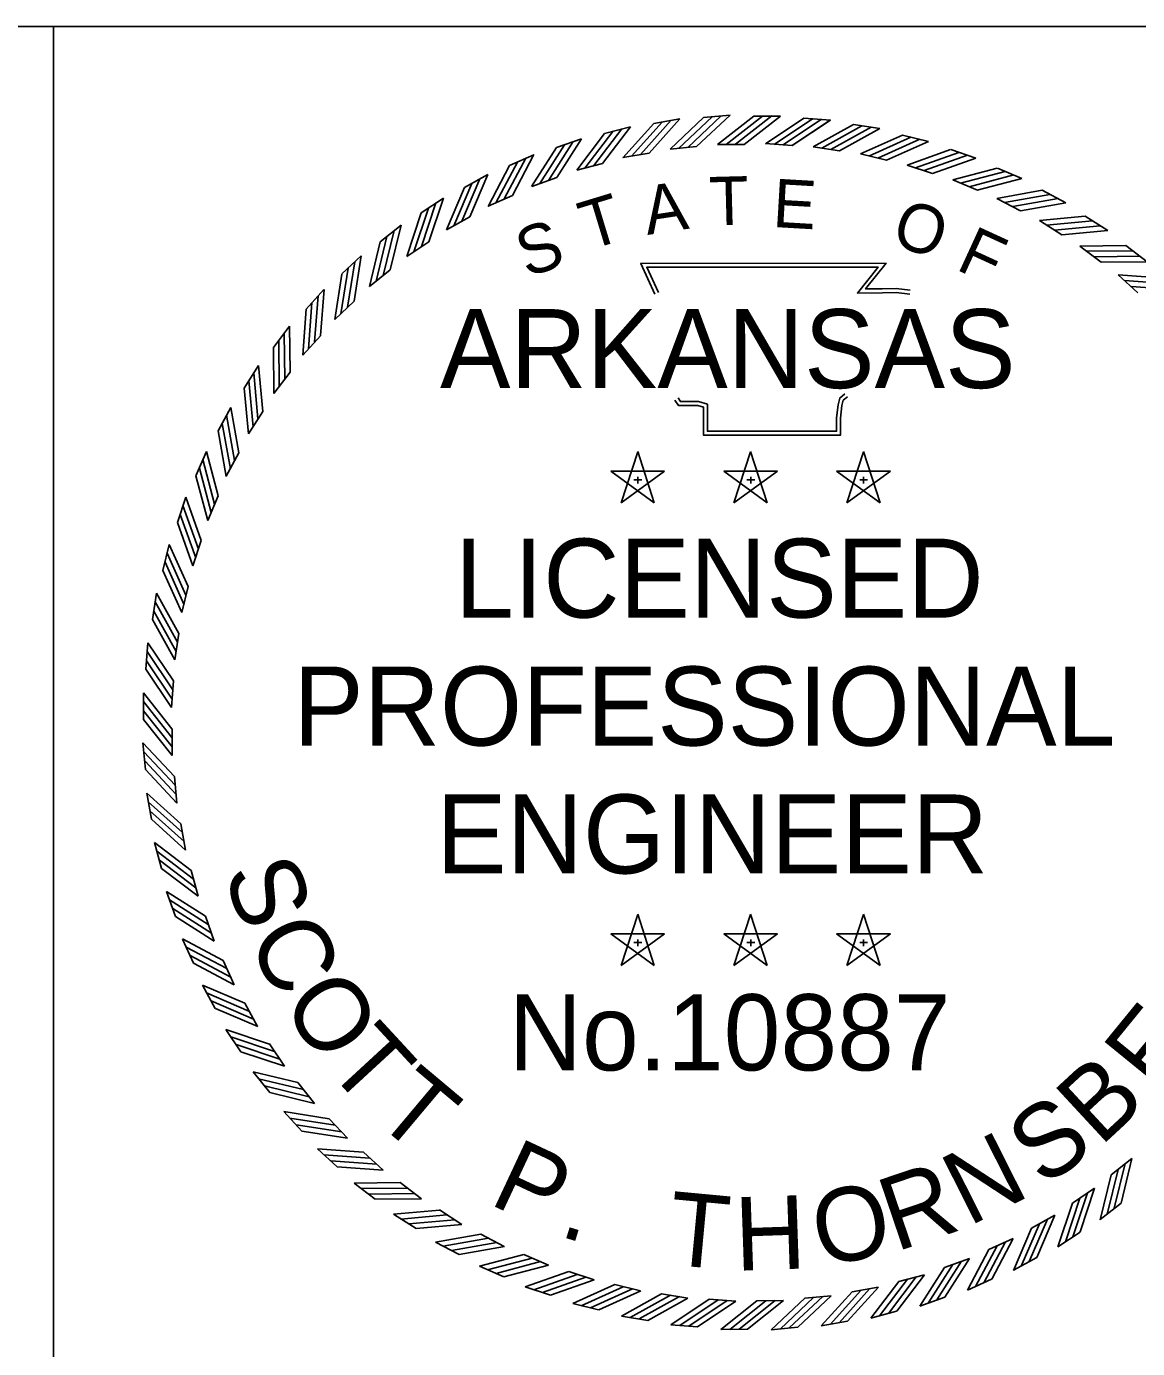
# Model space of a CAD drawing. Extents: x 0 to 1228740, y 0 to 152440.
# Drawn here: x 30.877 to 32.858, y 17.785 to 20.143 of the extents above; entities that cross this region are included whole.
import ezdxf

# ---------------------------------------------------------------- set-up
doc = ezdxf.new("R2010")
doc.units = 0
for name, color, linetype in [('R_Border', 7, 'Continuous'), ('R_No Plot', 7, 'Continuous'), ('STAMP', 7, 'Continuous'), ('STAMP_KLL', 7, 'Continuous')]:
    doc.layers.add(name, color=color, linetype=linetype)

# ---------------------------------------------------------------- blocks, each defined once
blk = doc.blocks.new('AR_SPT')
at = {"layer": 'R_No Plot'}
blk.add_lwpolyline([(-0.10028, 0.09468), (0.09697, 0.09468), (0.09697, -0.10257), (-0.10028, -0.10257)], close=True, dxfattribs=at)
at = {"layer": 'STAMP'}
for p, q in [((-0.01536, 0.08094), (-0.01165, 0.08159)), ((-0.00831, 0.08178), (-0.00456, 0.08212)), ((-0.00118, 0.08199), (0.00259, 0.08199)), ((0.00588, 0.08171), (0.00964, 0.08143)), ((0.00588, 0.08171), (0.00963, 0.08143)), ((0.01291, 0.08079), (0.01663, 0.08021)), ((-0.02912, 0.07752), (-0.02557, 0.07878)), ((-0.02231, 0.07951), (-0.01867, 0.08047)), ((0.01985, 0.0793), (0.02351, 0.07841)), ((-0.01972, 0.0761), (-0.016, 0.07675)), ((-0.01306, 0.07732), (-0.0093, 0.07766)), ((-0.00632, 0.07798), (-0.00254, 0.07798)), ((0.00045, 0.07809), (0.00422, 0.07781)), ((0.00046, 0.07809), (0.00422, 0.07781)), ((0.00721, 0.07763), (0.01094, 0.07705)), ((0.02665, 0.07724), (0.03022, 0.07605)), ((-0.03575, 0.07498), (-0.03232, 0.07652)), ((-0.02626, 0.07433), (-0.02261, 0.07529)), ((0.01391, 0.07662), (0.01758, 0.07573)), ((0.0205, 0.07506), (0.02409, 0.07387)), ((-0.04214, 0.07189), (-0.03885, 0.07372)), ((-0.03263, 0.07203), (-0.02907, 0.07329)), ((0.03325, 0.07463), (0.03671, 0.07314)), ((0.02694, 0.07296), (0.03042, 0.07148)), ((0.03961, 0.07148), (0.04293, 0.06971)), ((-0.04826, 0.06829), (-0.04512, 0.07038)), ((-0.03879, 0.06922), (-0.03535, 0.07076)), ((0.03319, 0.07034), (0.03653, 0.06857)), ((-0.0447, 0.0659), (-0.0414, 0.06773)), ((0.04568, 0.06781), (0.04886, 0.06578)), ((-0.05406, 0.0642), (-0.05111, 0.06654)), ((0.0392, 0.06721), (0.04238, 0.06517)), ((-0.05031, 0.06211), (-0.04717, 0.0642)), ((0.05144, 0.06366), (0.05443, 0.06137)), ((-0.0595, 0.05964), (-0.05675, 0.06221)), ((0.04492, 0.06359), (0.04792, 0.0613)), ((-0.05559, 0.05786), (-0.05263, 0.06021)), ((0.05033, 0.05951), (0.05313, 0.05698)), ((-0.06454, 0.05464), (-0.06202, 0.05744)), ((-0.0605, 0.0532), (-0.05775, 0.05578)), ((-0.06915, 0.04925), (-0.06687, 0.05224)), ((-0.06501, 0.04814), (-0.06248, 0.05094)), ((-0.07331, 0.04349), (-0.07128, 0.04667)), ((-0.06909, 0.04273), (-0.0668, 0.04573)), ((-0.07697, 0.03742), (-0.07521, 0.04074)), ((-0.07271, 0.03701), (-0.07067, 0.04018)), ((-0.08012, 0.03105), (-0.07864, 0.03452)), ((-0.07584, 0.031), (-0.07407, 0.03433)), ((-0.01763, 0.03448), (-0.01999, 0.02725)), ((-0.01529, 0.02725), (-0.01763, 0.03449)), ((-0.00166, 0.03448), (-0.00402, 0.02725)), ((0.00069, 0.02725), (-0.00166, 0.03449)), ((0.01431, 0.03448), (0.01196, 0.02725)), ((0.01666, 0.02725), (0.01432, 0.03449)), ((-0.01384, 0.03172), (-0.02144, 0.03173)), ((-0.02143, 0.03172), (-0.01528, 0.02725)), ((-0.01998, 0.02725), (-0.01383, 0.03172)), ((-0.01817, 0.0305), (-0.01704, 0.0305)), ((-0.01763, 0.03091), (-0.01763, 0.02996)), ((0.00214, 0.03172), (-0.00546, 0.03173)), ((-0.00546, 0.03172), (0.00069, 0.02725)), ((-0.00401, 0.02725), (0.00215, 0.03172)), ((-0.0022, 0.0305), (-0.00107, 0.0305)), ((-0.00165, 0.03091), (-0.00165, 0.02996)), ((0.01811, 0.03172), (0.01051, 0.03173)), ((0.01051, 0.03172), (0.01666, 0.02725)), ((0.01196, 0.02725), (0.01812, 0.03172)), ((0.01377, 0.0305), (0.0149, 0.0305)), ((0.01432, 0.03091), (0.01432, 0.02996)), ((-0.07846, 0.02475), (-0.07698, 0.02822)), ((-0.08274, 0.02446), (-0.08155, 0.02803)), ((-0.0848, 0.01766), (-0.08391, 0.02132)), ((-0.08056, 0.01831), (-0.07937, 0.02189)), ((-0.08212, 0.01172), (-0.08123, 0.01539)), ((-0.08629, 0.01072), (-0.0857, 0.01444)), ((-0.08313, 0.00502), (-0.08254, 0.00875)), ((-0.0872, 0.00368), (-0.08693, 0.00744)), ((-0.08358, -0.00173), (-0.08331, 0.00203)), ((-0.08753, -0.00341), (-0.08757, 0.00036)), ((-0.08348, -0.00851), (-0.08351, -0.00473)), ((-0.08728, -0.0105), (-0.08762, -0.00675)), ((-0.08281, -0.01525), (-0.08316, -0.01149)), ((-0.08643, -0.01755), (-0.08709, -0.01384)), ((-0.08159, -0.02191), (-0.08225, -0.01819)), ((-0.08501, -0.0245), (-0.08597, -0.02086)), ((-0.07983, -0.02845), (-0.08079, -0.0248)), ((-0.08302, -0.03131), (-0.08428, -0.02776)), ((-0.07753, -0.03482), (-0.07879, -0.03126)), ((-0.01763, -0.03101), (-0.01999, -0.03824)), ((-0.01529, -0.03823), (-0.01763, -0.031)), ((-0.00166, -0.03101), (-0.00402, -0.03824)), ((0.00069, -0.03823), (-0.00166, -0.031)), ((0.01431, -0.03101), (0.01196, -0.03824)), ((0.01666, -0.03823), (0.01432, -0.031)), ((-0.08048, -0.03794), (-0.08202, -0.03451)), ((-0.01384, -0.03377), (-0.02144, -0.03376)), ((-0.02143, -0.03377), (-0.01528, -0.03824)), ((-0.01998, -0.03823), (-0.01383, -0.03377)), ((-0.01817, -0.03498), (-0.01704, -0.03498)), ((-0.01763, -0.03458), (-0.01763, -0.03553)), ((0.00214, -0.03377), (-0.00546, -0.03376)), ((-0.00546, -0.03377), (0.00069, -0.03824)), ((-0.00401, -0.03823), (0.00215, -0.03377)), ((-0.0022, -0.03498), (-0.00107, -0.03498)), ((-0.00165, -0.03458), (-0.00165, -0.03553)), ((0.01811, -0.03377), (0.01051, -0.03376)), ((0.01051, -0.03377), (0.01666, -0.03824)), ((0.01196, -0.03823), (0.01812, -0.03377)), ((0.01377, -0.03498), (0.0149, -0.03498)), ((0.01432, -0.03458), (0.01432, -0.03553)), ((-0.07471, -0.04098), (-0.07626, -0.03754)), ((-0.07739, -0.04433), (-0.07921, -0.04104)), ((-0.0714, -0.04689), (-0.07322, -0.04359)), ((-0.07379, -0.05045), (-0.07588, -0.04732)), ((-0.0676, -0.0525), (-0.0697, -0.04936)), ((-0.06969, -0.05625), (-0.07203, -0.0533)), ((-0.06336, -0.05778), (-0.06571, -0.05483)), ((-0.06513, -0.06169), (-0.06771, -0.05894)), ((-0.0587, -0.06269), (-0.06128, -0.05994)), ((-0.06014, -0.06673), (-0.06293, -0.06421)), ((-0.05364, -0.0672), (-0.05644, -0.06467)), ((0.05228, -0.06555), (0.04933, -0.0679)), ((-0.05475, -0.07135), (-0.05774, -0.06906)), ((-0.04823, -0.07128), (-0.05123, -0.06899)), ((0.047, -0.06979), (0.04386, -0.07189)), ((-0.0425, -0.0749), (-0.04568, -0.07286)), ((0.05075, -0.07188), (0.0478, -0.07422)), ((-0.04899, -0.0755), (-0.05216, -0.07347)), ((0.04139, -0.07359), (0.03809, -0.07541)), ((-0.0365, -0.07803), (-0.03983, -0.07626)), ((0.04495, -0.07598), (0.04182, -0.07807)), ((-0.04291, -0.07916), (-0.04624, -0.0774)), ((0.03549, -0.0769), (0.03204, -0.07845)), ((-0.03025, -0.08065), (-0.03372, -0.07917)), ((0.02933, -0.07972), (0.02577, -0.08098)), ((0.03884, -0.07958), (0.03554, -0.0814)), ((-0.03655, -0.08231), (-0.04001, -0.08083)), ((-0.02381, -0.08275), (-0.02739, -0.08156)), ((0.02295, -0.08202), (0.0193, -0.08298)), ((-0.02995, -0.08493), (-0.03353, -0.08374)), ((-0.01722, -0.08431), (-0.02089, -0.08342)), ((0.01641, -0.08379), (0.0127, -0.08444)), ((0.03244, -0.08267), (0.02901, -0.08421)), ((-0.01052, -0.08532), (-0.01425, -0.08473)), ((-0.00376, -0.08577), (-0.00753, -0.0855)), ((0.00301, -0.08567), (-0.00076, -0.0857)), ((0.00975, -0.085), (0.00599, -0.08535)), ((0.02582, -0.08521), (0.02227, -0.08647)), ((-0.02316, -0.08699), (-0.02682, -0.0861)), ((-0.01622, -0.08848), (-0.01994, -0.08789)), ((0.019, -0.0872), (0.01536, -0.08816)), ((-0.00918, -0.08939), (-0.01294, -0.08912)), ((-0.00209, -0.08972), (-0.00586, -0.08976)), ((0.005, -0.08947), (0.00125, -0.08981)), ((0.01205, -0.08862), (0.00834, -0.08928))]:
    blk.add_line(p, q, dxfattribs=at)
for points in [[(-0.02262, 0.07529), (-0.01867, 0.08048)], [(-0.01972, 0.07609), (-0.01536, 0.08093)], [(-0.01853, 0.07629), (-0.01417, 0.08113)], [(-0.01725, 0.07655), (-0.01288, 0.08139)], [(-0.01601, 0.07675), (-0.01165, 0.08159)], [(-0.01306, 0.07731), (-0.00831, 0.08177)], [(-0.01185, 0.07741), (-0.00711, 0.08187)], [(-0.01055, 0.07756), (-0.00581, 0.08202)], [(-0.0093, 0.07766), (-0.00456, 0.08213)], [(-0.00632, 0.07798), (-0.00118, 0.08198)], [(-0.00511, 0.07797), (0.00003, 0.08197)], [(-0.0038, 0.078), (0.00134, 0.082)], [(-0.00255, 0.07798), (0.00259, 0.08199)], [(0.00045, 0.07808), (0.00587, 0.08171)], [(0.00045, 0.07808), (0.00587, 0.0817)], [(0.00166, 0.07798), (0.00708, 0.08161)], [(0.00166, 0.07798), (0.00708, 0.0816)], [(0.00296, 0.07792), (0.00839, 0.08154)], [(0.00297, 0.07792), (0.00838, 0.08154)], [(0.00422, 0.07781), (0.00964, 0.08144)], [(0.00422, 0.07781), (0.00963, 0.08143)], [(0.00721, 0.07763), (0.01291, 0.08079)], [(0.00841, 0.07743), (0.0141, 0.08059)], [(-0.02908, 0.07329), (-0.02557, 0.07878)], [(-0.02626, 0.07433), (-0.02231, 0.07951)], [(-0.02509, 0.07463), (-0.02114, 0.07981)], [(-0.02383, 0.07499), (-0.01988, 0.08017)], [(0.0097, 0.07726), (0.0154, 0.08041)], [(0.01094, 0.07705), (0.01664, 0.08021)], [(0.01391, 0.07662), (0.01985, 0.0793)], [(0.01508, 0.07632), (0.02102, 0.079)], [(0.01636, 0.07604), (0.0223, 0.07872)], [(-0.03264, 0.07203), (-0.02913, 0.07752)], [(-0.03149, 0.07242), (-0.02798, 0.07791)], [(-0.03027, 0.07289), (-0.02676, 0.07838)], [(0.01758, 0.07573), (0.02352, 0.07841)], [(0.0205, 0.07506), (0.02664, 0.07724)], [(0.02165, 0.07467), (0.02779, 0.07684)], [(-0.0388, 0.06921), (-0.03575, 0.07497)], [(-0.03769, 0.0697), (-0.03464, 0.07546)], [(-0.0365, 0.07026), (-0.03346, 0.07602)], [(-0.03536, 0.07076), (-0.03231, 0.07653)], [(0.0229, 0.07428), (0.02904, 0.07646)], [(0.02408, 0.07387), (0.03022, 0.07605)], [(-0.0425, 0.06713), (-0.03995, 0.07312)], [(-0.0414, 0.06773), (-0.03885, 0.07372)], [(0.02694, 0.07296), (0.03324, 0.07462)], [(0.02805, 0.07247), (0.03435, 0.07414)], [(0.02926, 0.07199), (0.03556, 0.07365)], [(0.03041, 0.07148), (0.03671, 0.07315)], [(-0.0447, 0.06589), (-0.04214, 0.07189)], [(-0.04364, 0.06647), (-0.04108, 0.07246)], [(0.03318, 0.07034), (0.0396, 0.07148)], [(-0.04823, 0.06351), (-0.04617, 0.0697)], [(-0.04718, 0.0642), (-0.04512, 0.07038)], [(0.03425, 0.06976), (0.04067, 0.0709)], [(0.03542, 0.06917), (0.04183, 0.07031)], [(0.03652, 0.06858), (0.04294, 0.06971)], [(-0.05031, 0.0621), (-0.04826, 0.06828)], [(-0.0493, 0.06276), (-0.04725, 0.06895)], [(0.03919, 0.06721), (0.04568, 0.06781)], [(-0.05363, 0.05944), (-0.05209, 0.06577)], [(-0.05264, 0.06021), (-0.0511, 0.06654)], [(0.04021, 0.06654), (0.04669, 0.06715)], [(0.04132, 0.06586), (0.04781, 0.06647)], [(0.04237, 0.06518), (0.04886, 0.06578)], [(-0.05559, 0.05786), (-0.05406, 0.06419)], [(-0.05464, 0.0586), (-0.0531, 0.06493)], [(0.04492, 0.06359), (0.05143, 0.06366)], [(-0.05775, 0.05578), (-0.05675, 0.06222)], [(0.04588, 0.06285), (0.05239, 0.06291)], [(0.04693, 0.06208), (0.05345, 0.06214)], [(-0.05961, 0.05401), (-0.05861, 0.06045)], [(-0.05868, 0.05493), (-0.05767, 0.06137)], [(-0.01521, 0.05679), (-0.01721, 0.06113), (0.01751, 0.06115), (0.01461, 0.05751), (0.01697, 0.05754), (0.01894, 0.05756), (0.02091, 0.05735)], [(-0.01471, 0.05702), (-0.01635, 0.06058), (0.01637, 0.0606), (0.01346, 0.05694), (0.01698, 0.05699), (0.01892, 0.05701), (0.02085, 0.0568)], [(0.04792, 0.06131), (0.05444, 0.06137)], [(-0.0605, 0.05319), (-0.0595, 0.05963)], [(0.05033, 0.05952), (0.05683, 0.05904)], [(0.05122, 0.05869), (0.05772, 0.05822)], [(-0.06334, 0.05002), (-0.06286, 0.05652)], [(-0.06249, 0.05094), (-0.06201, 0.05744)], [(0.05221, 0.05784), (0.05871, 0.05737)], [(-0.06501, 0.04814), (-0.06454, 0.05464)], [(-0.06419, 0.04903), (-0.06372, 0.05553)], [(-0.06757, 0.04474), (-0.06764, 0.05126)], [(-0.0668, 0.04573), (-0.06687, 0.05225)], [(-0.06909, 0.04273), (-0.06916, 0.04924)], [(-0.06834, 0.04368), (-0.06841, 0.0502)], [(-0.07136, 0.03913), (-0.07196, 0.04562)], [(-0.07067, 0.04018), (-0.07128, 0.04667)], [(-0.0727, 0.037), (-0.07331, 0.04349)], [(-0.07204, 0.03801), (-0.07265, 0.0445)], [(0.01204, 0.04223), (0.01145, 0.04175), (0.01125, 0.04103), (0.01106, 0.03923), (0.01106, 0.03683), (-0.00833, 0.03683), (-0.00833, 0.04007), (-0.00833, 0.04079), (-0.00912, 0.04103), (-0.01187, 0.04103), (-0.01236, 0.04178)], [(0.01169, 0.04266), (0.01096, 0.04207), (0.01071, 0.04113), (0.01051, 0.03926), (0.01051, 0.03738), (-0.00778, 0.03738), (-0.00778, 0.04007), (-0.00778, 0.0412), (-0.00903, 0.04158), (-0.01158, 0.04158), (-0.0119, 0.04208)], [(-0.07467, 0.03323), (-0.07581, 0.03964)], [(-0.07407, 0.03433), (-0.07521, 0.04075)], [(-0.07526, 0.03206), (-0.0764, 0.03847)], [(-0.07583, 0.03099), (-0.07697, 0.03741)], [(-0.07698, 0.02822), (-0.07864, 0.03452)], [(-0.07797, 0.02586), (-0.07964, 0.03216)], [(-0.07748, 0.02707), (-0.07915, 0.03337)], [(-0.07846, 0.02475), (-0.08012, 0.03105)], [(-0.07978, 0.0207), (-0.08196, 0.02685)], [(-0.07937, 0.02189), (-0.08155, 0.02803)], [(-0.08056, 0.01831), (-0.08274, 0.02445)], [(-0.08016, 0.01945), (-0.08234, 0.0256)], [(-0.08123, 0.01539), (-0.08391, 0.02133)], [(-0.08182, 0.01289), (-0.0845, 0.01883)], [(-0.08154, 0.01417), (-0.08422, 0.02011)], [(-0.08212, 0.01172), (-0.08479, 0.01766)], [(-0.08275, 0.00751), (-0.08591, 0.01321)], [(-0.08255, 0.00875), (-0.08571, 0.01445)], [(-0.08293, 0.00621), (-0.08609, 0.01191)], [(-0.08313, 0.00502), (-0.08629, 0.01072)], [(-0.08341, 0.00078), (-0.08703, 0.00619)], [(-0.08331, 0.00203), (-0.08693, 0.00744)], [(-0.08348, -0.00053), (-0.0871, 0.00489)], [(-0.08358, -0.00174), (-0.0872, 0.00368)], [(-0.08352, -0.00474), (-0.08757, 0.00036)], [(-0.08352, -0.00599), (-0.08757, -0.00089)], [(-0.08347, -0.0073), (-0.08753, -0.0022)], [(-0.08347, -0.00851), (-0.08753, -0.00341)], [(-0.08316, -0.01149), (-0.08762, -0.00675)], [(-0.08306, -0.01274), (-0.08752, -0.008)], [(-0.08291, -0.01404), (-0.08737, -0.0093)], [(-0.08281, -0.01525), (-0.08727, -0.0105)], [(-0.08225, -0.0182), (-0.08709, -0.01384)], [(-0.08205, -0.01944), (-0.08688, -0.01507)], [(-0.08179, -0.02072), (-0.08663, -0.01636)], [(-0.08159, -0.02192), (-0.08643, -0.01755)], [(-0.08079, -0.02481), (-0.08597, -0.02086)], [(-0.08048, -0.02602), (-0.08567, -0.02207)], [(-0.08012, -0.02728), (-0.0853, -0.02333)], [(-0.07983, -0.02845), (-0.08501, -0.02451)], [(-0.07879, -0.03127), (-0.08428, -0.02776)], [(-0.07838, -0.03246), (-0.08387, -0.02895)], [(-0.07792, -0.03368), (-0.08341, -0.03017)], [(-0.07753, -0.03483), (-0.08302, -0.03132)], [(-0.07626, -0.03755), (-0.08202, -0.0345)], [(-0.07576, -0.03869), (-0.08152, -0.03565)], [(-0.0752, -0.03988), (-0.08096, -0.03683)], [(-0.07471, -0.04099), (-0.08047, -0.03794)], [(-0.07322, -0.04359), (-0.07922, -0.04104)], [(-0.07263, -0.0447), (-0.07862, -0.04214)], [(-0.07197, -0.04583), (-0.07796, -0.04327)], [(-0.07139, -0.04689), (-0.07738, -0.04434)], [(-0.0697, -0.04937), (-0.07588, -0.04731)], [(-0.06901, -0.05042), (-0.07519, -0.04836)], [(-0.06826, -0.05149), (-0.07445, -0.04944)], [(-0.0676, -0.0525), (-0.07378, -0.05045)], [(-0.06571, -0.05483), (-0.07204, -0.0533)], [(-0.06493, -0.05582), (-0.07127, -0.05429)], [(-0.0641, -0.05683), (-0.07043, -0.05529)], [(-0.06336, -0.05778), (-0.06969, -0.05625)], [(-0.06128, -0.05995), (-0.06771, -0.05894)], [(-0.06043, -0.06087), (-0.06686, -0.05986)], [(-0.05951, -0.0618), (-0.06595, -0.0608)], [(-0.05869, -0.06269), (-0.06513, -0.06169)], [(-0.05644, -0.06468), (-0.06294, -0.06421)], [(-0.05552, -0.06553), (-0.06202, -0.06506)], [(-0.05453, -0.06638), (-0.06103, -0.06591)], [(-0.05364, -0.0672), (-0.06013, -0.06673)], [(0.05032, -0.06713), (0.04879, -0.07346)], [(0.05133, -0.06629), (0.04979, -0.07262)], [(0.05229, -0.06555), (0.05075, -0.07188)], [(-0.05123, -0.06899), (-0.05774, -0.06906)], [(0.04933, -0.0679), (0.0478, -0.07423)], [(-0.05024, -0.06976), (-0.05675, -0.06983)], [(-0.04918, -0.07054), (-0.0557, -0.0706)], [(0.04599, -0.07045), (0.04394, -0.07664)], [(0.04701, -0.06979), (0.04495, -0.07597)], [(-0.04823, -0.07128), (-0.05474, -0.07135)], [(-0.04568, -0.07287), (-0.05217, -0.07347)], [(0.04387, -0.07189), (0.04182, -0.07807)], [(0.04492, -0.0712), (0.04287, -0.07739)], [(-0.04463, -0.07355), (-0.05112, -0.07416)], [(-0.04351, -0.07423), (-0.05, -0.07484)], [(0.0392, -0.07482), (0.03664, -0.08081)], [(0.04033, -0.07416), (0.03777, -0.08015)], [(0.04139, -0.07358), (0.03884, -0.07958)], [(-0.0425, -0.0749), (-0.04899, -0.0755)], [(-0.03983, -0.07627), (-0.04624, -0.0774)], [(0.03809, -0.07541), (0.03554, -0.08141)], [(-0.03873, -0.07686), (-0.04514, -0.078)], [(-0.03756, -0.07745), (-0.04397, -0.07859)], [(-0.03649, -0.07803), (-0.04291, -0.07916)], [(0.03205, -0.07845), (0.02901, -0.08421)], [(0.0332, -0.07795), (0.03015, -0.08371)], [(0.03438, -0.07739), (0.03134, -0.08315)], [(0.03549, -0.0769), (0.03245, -0.08266)], [(-0.03372, -0.07917), (-0.04002, -0.08083)], [(-0.03257, -0.07967), (-0.03887, -0.08134)], [(-0.03136, -0.08016), (-0.03766, -0.08183)], [(0.02818, -0.08011), (0.02467, -0.0856)], [(0.02933, -0.07972), (0.02582, -0.08521)], [(-0.03025, -0.08065), (-0.03655, -0.08231)], [(-0.02739, -0.08156), (-0.03353, -0.08374)], [(-0.0262, -0.08197), (-0.03234, -0.08415)], [(0.02178, -0.08231), (0.01783, -0.0875)], [(0.02296, -0.08202), (0.01901, -0.0872)], [(0.02577, -0.08098), (0.02226, -0.08647)], [(0.02696, -0.08057), (0.02345, -0.08606)], [(-0.02495, -0.08235), (-0.03109, -0.08453)], [(-0.02381, -0.08275), (-0.02995, -0.08493)], [(-0.02088, -0.08342), (-0.02682, -0.0861)], [(-0.01967, -0.08373), (-0.02561, -0.08641)], [(-0.01839, -0.08401), (-0.02433, -0.08669)], [(0.01522, -0.08398), (0.01086, -0.08882)], [(0.01642, -0.08378), (0.01205, -0.08862)], [(0.01931, -0.08298), (0.01536, -0.08816)], [(0.02052, -0.08267), (0.01658, -0.08786)], [(-0.01721, -0.08431), (-0.02315, -0.08699)], [(-0.01425, -0.08474), (-0.01994, -0.0879)], [(-0.01301, -0.08494), (-0.01871, -0.0881)], [(-0.01171, -0.08512), (-0.01741, -0.08828)], [(-0.01052, -0.08532), (-0.01621, -0.08848)], [(-0.00752, -0.0855), (-0.01294, -0.08912)], [(-0.00627, -0.0856), (-0.01169, -0.08922)], [(-0.00497, -0.08567), (-0.01038, -0.08929)], [(-0.00376, -0.08577), (-0.00918, -0.08939)], [(-0.00076, -0.08571), (-0.00586, -0.08976)], [(0.00049, -0.08571), (-0.00461, -0.08976)], [(0.0018, -0.08567), (-0.0033, -0.08972)], [(0.00301, -0.08567), (-0.00209, -0.08972)], [(0.006, -0.08535), (0.00125, -0.08981)], [(0.00725, -0.08525), (0.0025, -0.08971)], [(0.00855, -0.0851), (0.0038, -0.08956)], [(0.00976, -0.085), (0.00501, -0.08946)], [(0.0127, -0.08444), (0.00834, -0.08928)], [(0.01394, -0.08424), (0.00958, -0.08907)]]:
    blk.add_lwpolyline(points, dxfattribs=at)
for s, height, rotation, p in [('T', 0.00686, 1.4789, (-0.00743, 0.0665)), ('T', 0.00685, 1.4789, (-0.00742, 0.06651)), ('E', 0.00685, 356.672, (0.00135, 0.0663)), ('A', 0.00685, 8.6788, (-0.01627, 0.06515)), ('T', 0.00685, 16.9015, (-0.02458, 0.06297)), ('O', 0.00685, 341.2218, (0.01798, 0.06395)), ('S', 0.00685, 19.7726, (-0.03329, 0.05906)), ('F', 0.00685, 335.3628, (0.02721, 0.06034)), ('S', 0.0104, 289.7007, (-0.07634, -0.0251)), ('C', 0.0104, 296.9967, (-0.07299, -0.03444)), ('O', 0.0104, 304.6575, (-0.06823, -0.0437)), ('E', 0.0104, 50.8144, (0.05577, -0.05653)), ('T', 0.0104, 312.6831, (-0.06197, -0.05264)), ('T', 0.0104, 319.9791, (-0.05524, -0.05993)), ('B', 0.0104, 42.7888, (0.04781, -0.064)), ('S', 0.0104, 35.4928, (0.03974, -0.06976)), ('P', 0.0104, 334.9359, (-0.03886, -0.07192)), ('N', 0.0104, 26.7376, (0.02917, -0.07525)), ('R', 0.0104, 18.712, (0.01886, -0.07882)), ('T', 0.0104, 354.6351, (-0.01362, -0.08054)), ('H', 0.0104, 1.9312, (-0.00374, -0.08147)), ('O', 0.0104, 10.6864, (0.00815, -0.08091)), ('.', 0.0104, 342.9615, (-0.02895, -0.07648))]:
    blk.add_text(s, height=height, rotation=rotation, dxfattribs=at).set_placement(p)
for s, height, p in [('ARKANSAS', 0.01118, (-0.0456, 0.04348)), ('LICENSED', 0.01118, (-0.04347, 0.01099)), ('PROFESSIONAL', 0.0111804, (-0.06637, -0.00712)), ('ENGINEER', 0.01118, (-0.04614, -0.02522)), ('No.10887', 0.010781, (-0.03591, -0.0531))]:
    blk.add_text(s, height=height, dxfattribs=at).set_placement(p)

msp = doc.modelspace()

# ---------------------------------------------------------------- linework, layer by layer
at = {"layer": 'R_Border'}
msp.add_line((29.1131, 20.1432), (33.4231, 20.1432), dxfattribs=at)

# ---------------------------------------------------------------- block references
at = {"layer": 'STAMP_KLL', "xscale": 12.6035, "yscale": 12.6035}
msp.add_blockref('AR_SPT', (32.1893, 18.9501), dxfattribs=at)

doc.saveas('drawing.dxf')
